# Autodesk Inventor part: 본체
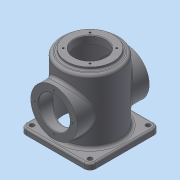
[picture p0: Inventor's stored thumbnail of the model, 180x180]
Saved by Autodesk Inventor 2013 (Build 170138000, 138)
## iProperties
Created: 2015-10
Part Number: 본체
Material: 일반
Document SubType Name: Modeling
Designer: Administrator
Density: 1 g/cm^3
Author: Administrator
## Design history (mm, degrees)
sketch "스케치1"
  geometry: L1 (-50, 60)-(50, 60); L2 (60, 50)-(60, -50); L3 (50, -60)-(-50, -60); L4 (-60, -50)-(-60, 50); A1 r 10 centre (-50, 50) between (-50, 60) and (-60, 50); A2 r 10 centre (-50, -50) between (-60, -50) and (-50, -60); A3 r 10 centre (50, -50) between (50, -60) and (60, -50); A4 r 10 centre (50, 50) between (60, 50) and (50, 60); 5 further points
  constraints: 8 end point, 8 point on circle, 8 tangent, 4 centre point, 4 point on line, 3 equal radius, 2 midpoint, 2 parallel, 2 perpendicular, 1 horizontal, 1 horizontal alignment, 1 vertical alignment
  dimensions: "d0" = 120 distance of point (-60, 60) point (60, 60); "d2" = 10 radius of A1
extrude "돌출1" new body sketch "스케치1" distance "d3" = 10; taper "d4" = 0 deg
sketch "스케치2"
  geometry: C1 r 50 at (0, 0); 1 further point
  constraints: 1 centre point, 1 coincident
  dimensions: "d5" = 100 diameter of C1
extrude "돌출2" join sketch "스케치2" distance "d7" = 110; taper "d8" = 0 deg
sketch "스케치3"
  geometry: C1 r 40 at (0, 0); 1 further point
  constraints: 1 centre point, 1 coincident
  dimensions: "d9" = 80 diameter of C1
extrude "돌출3" join sketch "스케치3" distance "d11" = 5; taper "d12" = 0 deg
sketch "스케치4"
  geometry: C1 r 40 at (0, 60); 1 further point
  constraints: 1 centre point, 1 vertical alignment
  dimensions: "d13" = 80 diameter of C1; "d15" = 60 distance of point (0, 0) C1.centre
extrude "돌출4" join sketch "스케치4" stored distance "d16" = 124; taper "d17" = 0 deg
node "작업 평면1"
sketch "스케치5"
  geometry: L1 (-39.988, 60.696)-(-39.988, 79.304); L2 (-39.988, 79.304)-(39.988, 79.304); L3 (39.988, 79.304)-(39.988, 60.696); L4 (39.988, 60.696)-(-39.988, 60.696); 4 further points
  constraints: 2 midpoint, 2 vertical alignment, 1 horizontal alignment, 2 other
  dimensions: "d19" = 70 distance of point (0, 0) point (0, 70)
feature "엠보싱1" sketch "스케치5" dims "d0" = 120, "d2" = 10, "d9" = 80, "d20" = 0.5, "d21" = 0
hole "구멍1" diameter "d24" = 54; stored, may be unused: countersink angle "d28" = 90 deg, drill point angle "d30" = 0 deg; dims "d22" = 10, "d23" = 10, "d25" = 6, "d26" = 90, "d27" = 112, "d29" = 125
hole "구멍2" diameter "d33" = 54; stored, may be unused: countersink angle "d37" = 90 deg, drill point angle "d39" = 0 deg; dims "d31" = 10, "d32" = 10, "d34" = 6, "d35" = 90, "d36" = 112, "d38" = 125
sketch "스케치6"
  geometry: A1 r 32.5 centre (0, 0) between (0, 32.5) and (0, -32.5); 3 further points
  constraints: 4 point on circle, 3 vertical alignment, 2 horizontal alignment, 1 centre point
  dimensions: "d40" = 60 distance of point (0, -60) A1.centre; "d41" = 65 diameter of A1
hole "구멍3" sketch "스케치6" at (0, 32.5), (0, -32.5), (-32.5, 0), (32.5, 0) diameter "d42" = 3.242; stored, may be unused: countersink angle "d46" = 90 deg, drill point angle "d48" = 118 deg; dims "d43" = 8, "d44" = 90, "d45" = 112, "d47" = 10
sketch "스케치7"
  geometry: A1 r 32.5 centre (0, 0) between (-22.981, 22.981) and (22.981, 22.981); 3 further points
  constraints: 4 point on circle, 2 horizontal alignment, 2 vertical alignment, 1 centre point, 1 coincident
  dimensions: "d49" = 65 diameter of A1; "d51" = 90 deg dimension on point (0, 0) A1.end A1.start
hole "구멍4" sketch "스케치7" at (-22.981, 22.981), (22.981, 22.981), (-22.981, -22.981), (22.981, -22.981) diameter "d53" = 3.242; stored, may be unused: countersink angle "d57" = 90 deg, drill point angle "d59" = 118 deg; dims "d54" = 8, "d55" = 90, "d56" = 112, "d58" = 10
sketch "스케치8"
  geometry: C1 r 4 at (-50, 50); C2 r 4 at (50, 50); C3 r 4 at (50, -50); C4 r 4 at (-50, -50); 1 further point
  constraints: 4 centre point, 3 equal radius, 2 horizontal alignment, 2 vertical alignment
  dimensions: "d60" = 100 distance of C2.centre C1.centre; "d62" = 50 horizontal distance of point (0, 0) C1.centre; "d63" = 100 distance of C4.centre C1.centre; "d64" = 50 horizontal distance of point (0, 0) C1.centre; "d65" = 8 diameter of C1
extrude "돌출5" cut sketch "스케치8" distance "d66" = 124; taper "d67" = 0 deg
chamfer "모따기1" distance "d68" = 1; stored, may be unused: second distance "d69" = 2, angle "d70" = 45 deg
chamfer "모따기2" distance "d71" = 3; stored, may be unused: second distance "d72" = 2, angle "d73" = 45 deg
fillet "모깎기1" dims "d74" = 5
fillet "모깎기2" dims "d75" = 5
fillet "모깎기3" dims "d76" = 5
fillet "모깎기4" dims "d77" = 3
fillet "모깎기5" dims "d78" = 3
node "솔리드1"
mirror "대칭1"
other parameters: "d18" = -13.25
